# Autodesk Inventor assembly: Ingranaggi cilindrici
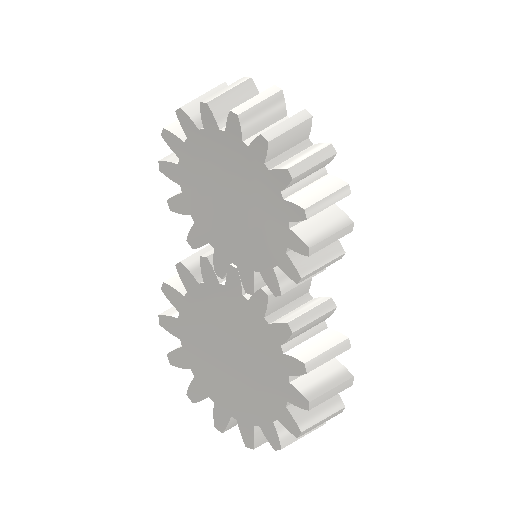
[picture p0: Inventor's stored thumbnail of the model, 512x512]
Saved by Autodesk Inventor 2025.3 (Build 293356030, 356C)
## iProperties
ClientObjectVersion: 1
Created: 2026-03
Part Number: Ingranaggi cilindrici
Document SubType Name: Assembly
Designer: R5800u
Categories: <?xml version="1.0" encoding="UTF-16"?> <MemberInstance><Categories><FamilyTemplate/><ParamToTemplateMap><ParamToTemplate><ParamToTemplate CategoryParameter="//
Author: R5800u
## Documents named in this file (3)
- C:\Users\R5800u\Desktop\robot mg90s\Assieme_ingranaggi_mg90s\Design Accelerator\Ingranaggi cilindrici2.iam
- C:\Users\R5800u\Desktop\robot mg90s\Assieme_ingranaggi_mg90s\Design Accelerator\Ingranaggio cilindrico12.ipt
- C:\Users\R5800u\Desktop\robot mg90s\Assieme_ingranaggi_mg90s\Design Accelerator\Ingranaggio cilindrico21.ipt
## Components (2 placed, 2 different names)
1. Ingranaggio cilindrico1:1 — Rotazione:1
2. Ingranaggio cilindrico2:1 — Rotazione:1
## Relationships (1: RelateRotation 1)
- Rotazione:1 [RelateRotation]: Ingranaggio cilindrico1:1 ↔ Ingranaggio cilindrico2:1
